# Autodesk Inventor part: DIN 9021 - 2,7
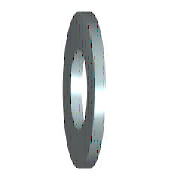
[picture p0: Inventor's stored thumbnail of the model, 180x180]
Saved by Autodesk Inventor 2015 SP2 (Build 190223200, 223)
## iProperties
IsCustomPart: 0
Created: 2012-02
Part Number: DIN 9021 - 2,7
Material: Stahl, weich
Description: Unterlegscheibe
Document SubType Name: Modeling
Standard: DIN 9021
Designer: Hübner
Standards Organization: DIN
Language: de-DE
Size Designation: 2,7
Categories: <MemberInstance><Categories><Category DisplayName="Verbindungselemente" InternalName="e4da775c-781d-43d5-af7c-5136215cf5a6" Mnemonic="FSTN"><Category DisplayNam
Density: 7.85 g/cm^3
Appearance: Halbpoliert
Author: Hübner
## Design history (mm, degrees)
sketch "Skizze"
  geometry: C1 r 4 at (0, 0); C2 r 1.35 at (0, 0); 1 further point
  constraints: 2 centre point, 2 coincident
  dimensions: "d0" = 2.7 diameter of C2 (= SD1); "d1" = 8 diameter of C1 (= SD2)
extrude "Körper" new body sketch "Skizze" distance "d2" = 0.8 (= SD); taper "d3" = 0 deg
workaxis "Work Axis1"
workplane "Work Plane1"
body "Solid1"
other parameters: "SD1" = 2.7 [user parameter; used in 1 equation term], "SD2" = 8 [user parameter; used in 1 equation term], "SD" = 0.8 [user parameter; used in 1 equation term], "d4" = 0, "d5" = 0, "d6" = 0, "d7" = 0, "NND" = 2.5 [user parameter]
